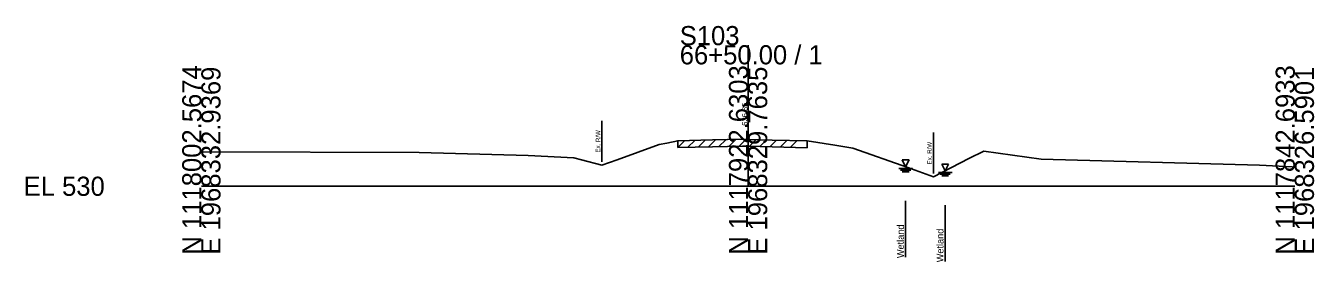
# Model space of a CAD drawing. Extents: x -26 to 163, y -10 to 24018.
# Drawn here: x -25.7 to 162.8, y 14488.9 to 14523.5 of the extents above; entities that cross this region are included whole.
import ezdxf

# ---------------------------------------------------------------- set-up
doc = ezdxf.new("R2010")
doc.units = 0
for name, color, linetype in [('RD_GPK_XS_Cell', 7, 'Continuous'), ('RD_XS_ExGround', 7, 'Continuous'), ('RD_XS_ExPaveRet', 7, 'Continuous'), ('RD_XS_ExRW', 7, 'Continuous'), ('RD_XS_EXWetland', 7, 'Continuous'), ('RD_XS_TX_Elev_EX', 7, 'Continuous')]:
    doc.layers.add(name, color=color, linetype=linetype)

msp = doc.modelspace()

# ---------------------------------------------------------------- linework, layer by layer
at = {"layer": 'RD_GPK_XS_Cell'}
for p, q in [((80, 14500), (80, 14520.62)), ((0, 14500), (80, 14500)), ((80, 14500), (160, 14500))]:
    msp.add_line(p, q, dxfattribs=at)
at = {"layer": 'RD_XS_ExGround'}
msp.add_lwpolyline([(0, 14505.02), (31.85, 14504.92), (47.8, 14504.5), (54.48, 14504.17), (55.64, 14503.88), (58.61, 14503.08), (60.83, 14503.88), (66.97, 14506.09), (68.11, 14506.28), (69.7, 14506.65), (74.81, 14506.77), (79.18, 14506.87), (80, 14506.85), (83.5, 14506.76), (88.62, 14506.63), (92.68, 14506.01), (95.34, 14505.59), (103.37, 14502.74), (107.13, 14501.36), (112.29, 14504.05), (114.51, 14505.14), (122.9, 14503.98), (154.83, 14503.06), (159.6, 14502.82), (160, 14502.81)], dxfattribs=at)
at = {"layer": 'RD_XS_ExPaveRet'}
for p, q in [((69.7, 14505.65), (70.73, 14506.68)), ((69.7, 14505.65), (69.7, 14506.65)), ((69.7, 14505.65), (74.81, 14505.77)), ((71.2, 14505.69), (72.23, 14506.71)), ((72.7, 14505.72), (73.73, 14506.74)), ((74.2, 14505.75), (75.23, 14506.78)), ((74.81, 14505.77), (79.18, 14505.87)), ((75.7, 14505.79), (76.73, 14506.81)), ((77.2, 14505.83), (78.23, 14506.85)), ((78.7, 14505.86), (79.7, 14506.86)), ((79.18, 14505.87), (80, 14505.85)), ((80, 14505.85), (83.5, 14505.76)), ((80.2, 14505.85), (81.18, 14506.82)), ((81.7, 14505.81), (82.68, 14506.78)), ((83.2, 14505.77), (84.18, 14506.74)), ((83.5, 14505.76), (88.62, 14505.63)), ((84.7, 14505.73), (85.68, 14506.7)), ((86.2, 14505.69), (87.18, 14506.67)), ((88.62, 14506.63), (88.62, 14505.63))]:
    msp.add_line(p, q, dxfattribs=at)
at = {"layer": 'RD_XS_ExRW'}
for p, q in [((58.61, 14509.58), (58.61, 14503.58)), ((107.13, 14507.86), (107.13, 14501.86))]:
    msp.add_line(p, q, dxfattribs=at)
at = {"layer": 'RD_XS_EXWetland'}
for p, q in [((102.55, 14503.86), (103.05, 14502.86)), ((103.55, 14503.86), (102.55, 14503.86)), ((103.05, 14502.86), (103.55, 14503.86)), ((102.05, 14502.61), (104.05, 14502.61)), ((102.3, 14502.36), (103.8, 14502.36)), ((102.55, 14502.11), (103.55, 14502.11)), ((107.84, 14502), (109.84, 14502)), ((108.34, 14503.25), (108.84, 14502.25)), ((109.34, 14503.25), (108.34, 14503.25)), ((108.84, 14502.25), (109.34, 14503.25)), ((108.09, 14501.75), (109.59, 14501.75)), ((108.34, 14501.5), (109.34, 14501.5)), ((103.05, 14497.86), (103.05, 14489.61)), ((108.84, 14497.25), (108.84, 14489))]:
    msp.add_line(p, q, dxfattribs=at)

# ---------------------------------------------------------------- texts
at = {"layer": 'RD_GPK_XS_Cell'}
for s, p in [('S103', (70, 14520.62)), ('66+50.00 / 1', (70, 14517.82)), ('EL 530', (-26, 14498.6))]:
    msp.add_text(s, height=2.8, dxfattribs=at).set_placement(p)
for s, p in [('N 1118002.5674', (0, 14490)), ('E 1968332.9369', (2.8, 14490)), ('N 1117922.6303', (80, 14490)), ('E 1968329.7635', (82.8, 14490)), ('N 1117842.6933', (160, 14490)), ('E 1968326.5901', (162.8, 14490))]:
    msp.add_text(s, height=2.8, rotation=90, dxfattribs=at).set_placement(p)
at = {"layer": 'RD_XS_ExRW'}
for p in [(58.36, 14504.92), (106.88, 14503.2)]:
    msp.add_text('Ex. R/W ', height=0.65, rotation=90, dxfattribs=at).set_placement(p)
at = {"layer": 'RD_XS_EXWetland'}
for p in [(102.8, 14489.5), (108.59, 14488.89)]:
    msp.add_text('Wetland ', height=1, rotation=90, dxfattribs=at).set_placement(p)
at = {"layer": 'RD_XS_TX_Elev_EX'}
msp.add_text('536.85', height=0.8, rotation=90, dxfattribs=at).set_placement((79.9, 14508.85))

doc.saveas('drawing.dxf')
